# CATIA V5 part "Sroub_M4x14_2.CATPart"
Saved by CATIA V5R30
Part number: Sroub_M4x14_2
Definition: 2025_05_12_09_08_15_0897
Nomenclature: 2025_05_12_09_08_15_0897
Source: Unknown
Description: PART--DESC
Bounding box of the stored display mesh (mm): x -97.5 to -90.5, y 30.01 to 36.99, z -5 to 9
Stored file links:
  E:\Bakalarka\Model\Forma_v7\Sroub_M4x14_2.CATPart
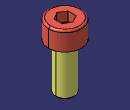
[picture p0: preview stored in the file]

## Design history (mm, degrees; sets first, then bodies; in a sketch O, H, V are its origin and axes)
Body1 "E2716_16B_NAUO3#E1200_4x10;Importiert1" (main body)
  Solid1: solid without history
